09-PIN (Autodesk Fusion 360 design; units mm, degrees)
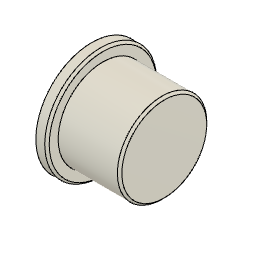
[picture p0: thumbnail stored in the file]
sketch "スケッチ" plane through (0, 0, 0) normal (0, 0, 1) x axis (1, 0, 0)
  line L1 (0, 5) -> (0, 0)
  line L2 (1, 5) -> (0, 5)
  line L3 (1, 4) -> (1, 5)
  line L4 (6.5, 4) -> (1, 4)
  line L5 (6.5, 0) -> (6.5, 4)
  line L6 (0, 0) -> (6.5, 0)
  point P1 (0, 0)
  point P2 (0, 0)
  point P8 (0, 0)
  point P3 (0, 5)
  point P4 (1, 5)
  point P5 (1, 4)
  point P6 (6.5, 4)
  coincident P1 P2
  vertical L1
  perpendicular L1 L2
  perpendicular L2 L3
  perpendicular L3 L4
  perpendicular L4 L5
  coincident P1 P8
  horizontal L6
  dimension "d1" = 8
  dimension "d2" = 10
  dimension "d3" distance P3 P4 = 1
  dimension "d4" distance P5 P6 = 5.5
revolve "回転" sketch "スケッチ" AlongAngle 360
chamfer "面取り" distance 0.2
